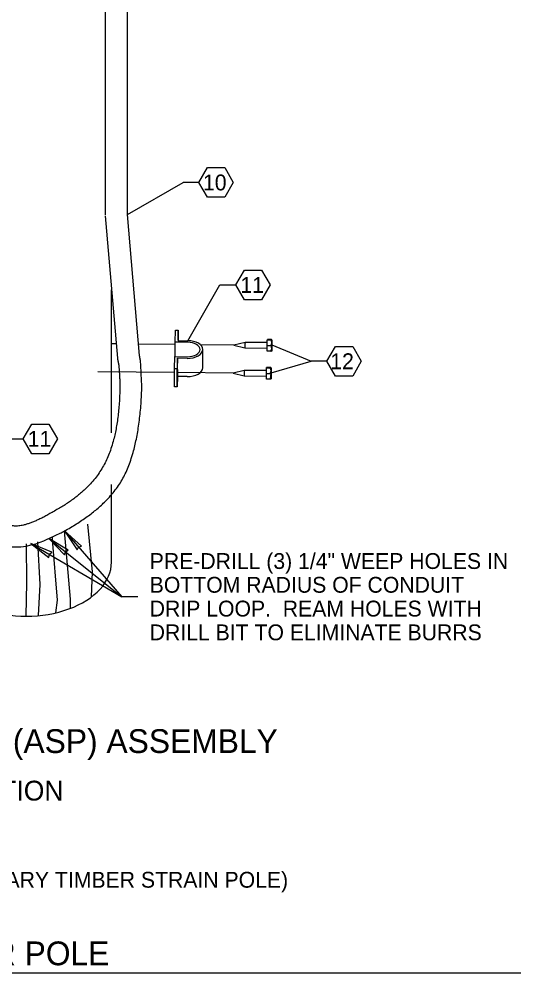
# Model space of a CAD drawing. Extents: x 99862 to 103151, y 100000 to 105076.
# Drawn here: x 101527 to 102027, y 103000 to 103962 of the extents above; entities that cross this region are included whole.
import ezdxf

# ---------------------------------------------------------------- set-up
doc = ezdxf.new("R2010")
doc.units = 0
for name, color, linetype in [('Level 1', 7, 'Continuous'), ('Level 15', 7, 'Continuous'), ('Level 16', 7, 'Continuous'), ('Level 20', 7, 'Continuous'), ('Level 28', 7, 'Continuous'), ('Level 31', 7, 'Continuous'), ('Level 42', 7, 'Continuous')]:
    doc.layers.add(name, color=color, linetype=linetype)

msp = doc.modelspace()

# ---------------------------------------------------------------- linework, layer by layer
at = {"layer": 'Level 1'}
msp.add_lwpolyline([(99862, 102999.5), (103151, 102999.5), (103151, 105075.5), (99862, 105075.5)], close=True, dxfattribs=at)
at = {"layer": 'Level 15'}
for p, q in [((101636.38, 103765.03), (101692.67, 103797.53)), ((101708.67, 103797.53), (101692.67, 103797.53)), ((101697.38, 103637.79), (101729.88, 103694.08)), ((101729.88, 103694.08), (101745.88, 103694.08)), ((101782.39, 103633.48), (101821.89, 103617.02)), ((101781.62, 103605.22), (101821.89, 103617.02)), ((101837.89, 103617.02), (101821.89, 103617.02)), ((101515.2, 103538.65), (101531.2, 103538.65)), ((101572.85, 103445.67), (101630.94, 103379.32)), ((101538.88, 103433.07), (101630.94, 103379.32)), ((101556.99, 103438.21), (101630.94, 103379.32)), ((101646.94, 103379.32), (101630.94, 103379.32))]:
    msp.add_line(p, q, dxfattribs=at)
for points in [[(101572.86, 103445.66), (101585.64, 103426.52), (101587.19, 103429.28), (101590.14, 103430.45)], [(101538.88, 103433.07), (101557.09, 103418.99), (101557.69, 103422.1), (101560.1, 103424.14)], [(101556.99, 103438.21), (101572.99, 103421.65), (101574.03, 103424.64), (101576.71, 103426.32)]]:
    msp.add_lwpolyline(points, close=True, dxfattribs=at)
at = {"layer": 'Level 16'}
for p, q in [((101625.04, 103634.47), (101620.33, 103634.51)), ((101684.68, 103633.93), (101647.64, 103634.26)), ((101743.92, 103633.39), (101710.14, 103633.69)), ((101683.94, 103605.66), (101606.54, 103606.37)), ((101743.15, 103605.12), (101686.87, 103605.63))]:
    msp.add_line(p, q, dxfattribs=at)
at = {"layer": 'Level 20'}
for points in [[(101708.67, 103797.53), (101717.33, 103812.53), (101734.66, 103812.53), (101743.3, 103797.53), (101734.66, 103782.54), (101717.33, 103782.54), (101708.67, 103797.53)], [(101745.88, 103694.08), (101754.54, 103709.08), (101771.86, 103709.08), (101780.5, 103694.08), (101771.86, 103679.09), (101754.54, 103679.09), (101745.88, 103694.08)], [(101837.89, 103617.02), (101846.55, 103632.02), (101863.87, 103632.02), (101872.51, 103617.02), (101863.87, 103602.02), (101846.55, 103602.02), (101837.89, 103617.02)], [(101531.2, 103538.65), (101539.86, 103553.65), (101557.18, 103553.65), (101565.82, 103538.65), (101557.18, 103523.65), (101539.86, 103523.65), (101531.2, 103538.65)]]:
    msp.add_lwpolyline(points, dxfattribs=at)
at = {"layer": 'Level 28'}
for p, q in [((101684.68, 103636.28), (101685.01, 103648.46)), ((101685.01, 103648.46), (101687.82, 103648.44)), ((101687.82, 103648.44), (101687.53, 103637.88)), ((101687.82, 103637.88), (101687.82, 103648.44)), ((101697.33, 103636.17), (101684.68, 103636.28)), ((101684.68, 103621.67), (101684.68, 103636.28)), ((101687.53, 103637.88), (101697.38, 103637.79)), ((101755.19, 103636.1), (101743.92, 103633.39)), ((101777.63, 103635.89), (101755.19, 103636.1)), ((101777.58, 103632.48), (101777.66, 103638.38)), ((101777.66, 103638.38), (101777.75, 103638.98)), ((101781.44, 103638.35), (101777.66, 103638.38)), ((101781.53, 103638.94), (101777.75, 103638.98)), ((101782.36, 103638.66), (101782.31, 103638.72)), ((101782.36, 103638.64), (101782.33, 103638.69)), ((101712.6, 103610.49), (101712.6, 103628.86)), ((101743.92, 103633.39), (101755.14, 103630.47)), ((101755.14, 103630.47), (101777.58, 103630.27)), ((101781.35, 103632.45), (101777.58, 103632.48)), ((101777.58, 103627.18), (101777.58, 103632.48)), ((101781.35, 103627.15), (101777.58, 103627.18)), ((101683.94, 103609.49), (101684.28, 103621.67)), ((101684.28, 103621.67), (101696.93, 103621.56)), ((101687.05, 103620.02), (101686.76, 103609.47)), ((101687.05, 103601.65), (101687.05, 103620.02)), ((101696.89, 103619.93), (101687.05, 103620.02)), ((101686.76, 103609.47), (101683.94, 103609.49)), ((101683.94, 103591.12), (101683.94, 103609.49)), ((101686.76, 103591.1), (101686.76, 103609.47)), ((101754.42, 103607.83), (101743.15, 103605.12)), ((101776.85, 103607.63), (101754.42, 103607.83)), ((101776.8, 103604.22), (101776.89, 103610.12)), ((101776.89, 103610.12), (101776.98, 103610.71)), ((101780.67, 103610.08), (101776.89, 103610.12)), ((101780.76, 103610.68), (101776.98, 103610.71)), ((101781.59, 103610.4), (101781.53, 103610.46)), ((101781.58, 103610.37), (101781.56, 103610.43)), ((101687.05, 103601.65), (101686.76, 103591.1)), ((101696.89, 103601.56), (101687.05, 103601.65)), ((101743.15, 103605.12), (101754.37, 103602.21)), ((101754.37, 103602.21), (101776.8, 103602)), ((101780.58, 103604.18), (101776.8, 103604.22)), ((101776.8, 103598.92), (101776.8, 103604.22)), ((101780.58, 103598.88), (101776.8, 103598.92)), ((101686.76, 103591.1), (101683.94, 103591.12))]:
    msp.add_line(p, q, dxfattribs=at)
for centre, major_axis, ratio, start_param, end_param in [((101697.13, 103628.86), (-12.66, 0), 0.57735, 3.141593, 4.696601), ((101697.13, 103628.86), (15.47, 0), 0.57735, 0, 1.555009), ((101755.17, 103633.28), (-0.03, -2.81), 0.01289, 3.141593, 5.327927), ((101782.31, 103633.04), (-0.05, -5.62), 0.01289, 4.28073, 5.327927), ((101782.31, 103633.04), (-0.05, -5.62), 0.01289, 3.233532, 4.28073), ((101782.31, 103633.04), (-0.05, -5.62), 0.01289, 3.128701, 3.233532), ((101782.31, 103633.04), (-0.05, -5.62), 0.01289, 2.186335, 3.128701), ((101782.31, 103633.04), (-0.05, -5.62), 0.01289, 1.139137, 2.186335), ((101697.13, 103628.86), (15.47, 0), 0.57735, 4.696601, 6.283185), ((101697.13, 103628.86), (-12.66, 0), 0.57735, 1.555009, 3.141593), ((101755.17, 103633.28), (-0.03, -2.81), 0.01289, 5.327927, 6.283185), ((101782.31, 103633.04), (0.05, 5.62), 0.01289, 2.186335, 3.154484), ((101782.31, 103633.04), (0.05, 5.62), 0.01289, 3.154484, 3.233532), ((101782.31, 103633.04), (-0.05, -5.62), 0.01289, 0.09194, 1.139137), ((101686.9, 103605.63), (0.03, 2.95), 0.01289, 0, 3.141593), ((101686.9, 103605.63), (0.03, 2.95), 0.01289, 3.141593, 5.327927), ((101686.9, 103605.63), (0.03, 2.95), 0.01289, 5.327927, 6.283185), ((101697.13, 103610.49), (15.47, 0), 0.57735, 4.696601, 6.283185), ((101754.39, 103605.02), (-0.03, -2.81), 0.01289, 3.141593, 5.327927), ((101781.54, 103604.77), (-0.05, -5.62), 0.01289, 4.28073, 5.327927), ((101781.54, 103604.77), (-0.05, -5.62), 0.01289, 3.233532, 4.28073), ((101781.54, 103604.77), (-0.05, -5.62), 0.01289, 3.128701, 3.233532), ((101781.54, 103604.77), (-0.05, -5.62), 0.01289, 1.139137, 2.186335), ((101781.54, 103604.77), (-0.05, -5.62), 0.01289, 2.186335, 3.128701), ((101754.39, 103605.02), (-0.03, -2.81), 0.01289, 5.327927, 6.283185), ((101781.54, 103604.77), (0.05, 5.62), 0.01289, 2.186335, 3.154484), ((101781.54, 103604.77), (0.05, 5.62), 0.01289, 3.154484, 3.233532), ((101781.54, 103604.77), (-0.05, -5.62), 0.01289, 0.09194, 1.139137)]:
    msp.add_ellipse(centre, major_axis=major_axis, ratio=ratio, start_param=start_param, end_param=end_param, dxfattribs=at)
for points in [[(101781.35, 103632.45), (101781.65, 103633.3), (101781.95, 103634.16), (101782.25, 103635.02)], [(101781.44, 103638.35), (101781.74, 103638.43), (101782.04, 103638.52), (101782.34, 103638.6)], [(101782.27, 103635.39), (101782.25, 103636.44), (101781.98, 103637.42), (101781.44, 103638.35)], [(101782.33, 103638.69), (101782.07, 103638.78), (101781.8, 103638.86), (101781.53, 103638.94)], [(101781.35, 103627.15), (101781.64, 103627.96), (101781.93, 103628.78), (101782.22, 103629.6)], [(101782.24, 103627.39), (101781.95, 103627.31), (101781.65, 103627.23), (101781.35, 103627.15)], [(101782.22, 103629.79), (101782.1, 103630.36), (101781.97, 103630.93), (101781.85, 103631.5)], [(101780.58, 103604.18), (101780.88, 103605.04), (101781.18, 103605.9), (101781.47, 103606.75)], [(101780.67, 103610.08), (101780.97, 103610.17), (101781.27, 103610.25), (101781.56, 103610.34)], [(101781.5, 103607.13), (101781.48, 103608.17), (101781.21, 103609.16), (101780.67, 103610.08)], [(101781.56, 103610.43), (101781.29, 103610.51), (101781.03, 103610.6), (101780.76, 103610.68)], [(101780.58, 103598.88), (101780.87, 103599.7), (101781.16, 103600.52), (101781.45, 103601.34)], [(101781.47, 103599.13), (101781.17, 103599.05), (101780.88, 103598.96), (101780.58, 103598.88)], [(101781.45, 103601.52), (101781.33, 103602.09), (101781.2, 103602.66), (101781.08, 103603.23)]]:
    msp.add_open_spline(points, degree=2, dxfattribs=at)
at = {"layer": 'Level 31'}
for p, q in [((101620.33, 103544.8), (101620.33, 103689.23)), ((101620.33, 103414.17), (101620.33, 103492.49))]:
    msp.add_line(p, q, dxfattribs=at)
for points in [[(101600.29, 103379.16), (101601.12, 103404.37), (101596.36, 103452.66)], [(101578.85, 103367.5), (101579.12, 103376.73), (101572.98, 103445.74)], [(101534.08, 103359.66), (101534.83, 103393.78), (101534.4, 103432.68)], [(101546.74, 103360.22), (101548.34, 103391.66), (101546.13, 103434.65)], [(101564.26, 103363.04), (101565.79, 103375.71), (101560.81, 103437.21), (101560.95, 103439.9)]]:
    msp.add_lwpolyline(points, dxfattribs=at)
msp.add_ellipse((101534.5, 103414.17), major_axis=(85.83, 0), ratio=0.635085, start_param=3.14158, end_param=6.283185, dxfattribs=at)
at = {"layer": 'Level 42'}
for p, q in [((101613.88, 104134.92), (101613.88, 103764.69)), ((101636.38, 103765.03), (101636.38, 104134.92)), ((101613.91, 103763.88), (101626.26, 103620.24)), ((101648.61, 103622.96), (101636.38, 103765.18))]:
    msp.add_line(p, q, dxfattribs=at)
for points, degree in [([(101626.3, 103619.97), (101627.38, 103615.06), (101628.1, 103609.99), (101628.86, 103594.47)], 2), ([(101651.02, 103589.78), (101649.97, 103614.95), (101649.38, 103619.09), (101648.59, 103623.16)], 2), ([(101628.86, 103594.47), (101628.59, 103543.4), (101599.14, 103485.44), (101561.58, 103465.14)], 2), ([(101572.84, 103445.66), (101617.33, 103470.15), (101648.99, 103532.34), (101651.02, 103589.78)], 2), ([(101561.56, 103465.13), (101534.12, 103448.88), (101506.88, 103452.72), (101482.7, 103482.36)], 2), ([(101466.89, 103463.11), (101489.07, 103435.58), (101526.2, 103423.52), (101564.01, 103441.33), (101568.49, 103443.21), (101571.5, 103444.91), (101572.85, 103445.67)], 3)]:
    msp.add_open_spline(points, degree=degree, dxfattribs=at)

# ---------------------------------------------------------------- texts
at = {"layer": 'Level 20'}
for s, height, p in [('10', 16, (101712.74, 103789.53)), ('11', 16, (101750.47, 103686.08)), ('12', 16, (101841.27, 103609.02)), ('11', 16, (101535.79, 103530.65)), ('ACCESSIBLE PEDESTRIAN SIGNAL (ASP) ASSEMBLY', 24, (100969.65, 103221.54)), ('WOOD POLE INSTALLATION', 20, (101209.31, 103173.54)), ('(ACCESSIBLE PEDESTRIAN PUSHBUTTON - TEMPORARY TIMBER STRAIN POLE)', 16, (100965.32, 103085.54)), ('TEMPORARY TIMBER POLE', 24, (101190.29, 103007.24))]:
    msp.add_text(s, height=height, dxfattribs=at).set_placement(p)
for s, p in [('PRE-DRILL (3) 1/4" WEEP HOLES IN', (101658.94, 103407.33)), ('BOTTOM RADIUS OF CONDUIT', (101658.94, 103383.33)), ('DRIP LOOP.  REAM HOLES WITH', (101658.94, 103359.33)), ('DRILL BIT TO ELIMINATE BURRS', (101658.94, 103335.33))]:
    msp.add_text(s, height=16, rotation=360, dxfattribs=at).set_placement(p)

doc.saveas('drawing.dxf')
